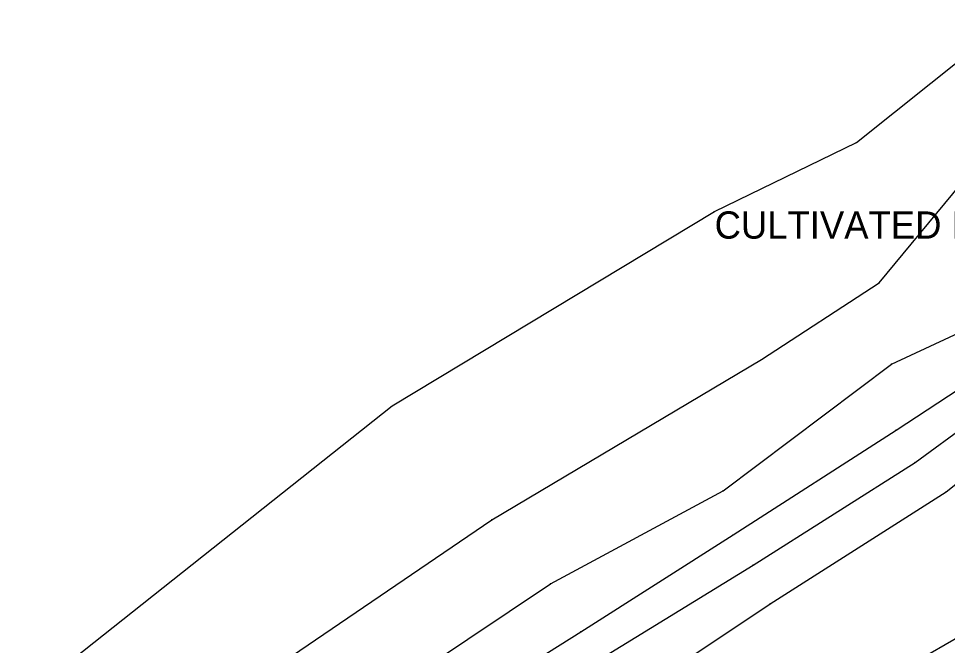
# Model space of a CAD drawing. Extents: x 1419505 to 1434054, y 1956910 to 1968644.
# Drawn here: x 1422840.8 to 1423011.2, y 1959040 to 1959155 of the extents above; entities that cross this region are included whole.
import ezdxf

# ---------------------------------------------------------------- set-up
doc = ezdxf.new("R2010")
doc.units = 0
for name, color, linetype in [('S_BREAKLINE', 7, 'Continuous'), ('S_DITCHLINE', 7, 'Continuous'), ('S_GRD_PT_SYM', 7, 'Continuous'), ('S_MSC_PT_SYM', 7, 'Continuous'), ('S_SURVEY_TEXT_ANNOT', 7, 'Continuous')]:
    doc.layers.add(name, color=color, linetype=linetype)

msp = doc.modelspace()

# ---------------------------------------------------------------- linework, layer by layer
at = {"layer": 'S_BREAKLINE'}
for p, q in [((1422994.5276, 1959132.2688), (1423022.9164, 1959155.0183)), ((1422998.6778, 1959106.5561), (1423022.2564, 1959135.109)), ((1422968.4779, 1959119.635), (1422994.5276, 1959132.2688)), ((1422909.3401, 1959083.9587), (1422968.4779, 1959119.635)), ((1422977.0964, 1959092.4572), (1422998.6778, 1959106.5561)), ((1423000.908, 1959091.6272), (1423029.8858, 1959105.094)), ((1422927.6052, 1959063.1023), (1422977.0964, 1959092.4572)), ((1422970.015, 1959068.3897), (1423000.908, 1959091.6272)), ((1423010.9586, 1959068.1907), (1423034.6522, 1959087.3959)), ((1422840.7776, 1959029.6612), (1422909.3401, 1959083.9587)), ((1422938.3659, 1959051.3316), (1422970.015, 1959068.3897)), ((1422978.6695, 1959047.6883), (1423010.9586, 1959068.1907)), ((1422864.9112, 1959020.4656), (1422927.6052, 1959063.1023)), ((1422881.2152, 1959013.1311), (1422938.3659, 1959051.3316)), ((1422950.6087, 1959028.9581), (1422978.6695, 1959047.6883)), ((1422987.9141, 1959027.032), (1423022.4534, 1959046.9853))]:
    msp.add_line(p, q, dxfattribs=at)
at = {"layer": 'S_DITCHLINE'}
for p, q in [((1423001.755, 1959079.5054), (1423029.9539, 1959098.0626)), ((1423005.2653, 1959073.577), (1423033.1021, 1959094.1543)), ((1422971.8951, 1959060.3062), (1423001.755, 1959079.5054)), ((1422975.5353, 1959054.7468), (1423005.2653, 1959073.577)), ((1422943.9453, 1959042.53), (1422971.8951, 1959060.3062)), ((1422945.9684, 1959036.6096), (1422975.5353, 1959054.7468)), ((1422890.9719, 1959009.3679), (1422943.9453, 1959042.53))]:
    msp.add_line(p, q, dxfattribs=at)
at = {"layer": 'S_GRD_PT_SYM'}
for points in [[(1422994.5276, 1959132.2688), (1422994.5276, 1959132.3188), (1422994.5276, 1959132.2688), (1422994.4776, 1959132.2688), (1422994.5276, 1959132.2688), (1422994.5276, 1959132.2188), (1422994.5276, 1959132.2688), (1422994.5776, 1959132.2688)], [(1422968.4779, 1959119.635), (1422968.4779, 1959119.685), (1422968.4779, 1959119.635), (1422968.4279, 1959119.635), (1422968.4779, 1959119.635), (1422968.4779, 1959119.585), (1422968.4779, 1959119.635), (1422968.5279, 1959119.635)], [(1422998.6778, 1959106.5561), (1422998.6778, 1959106.6061), (1422998.6778, 1959106.5561), (1422998.6278, 1959106.5561), (1422998.6778, 1959106.5561), (1422998.6778, 1959106.5061), (1422998.6778, 1959106.5561), (1422998.7278, 1959106.5561)], [(1422977.0964, 1959092.4572), (1422977.0964, 1959092.5072), (1422977.0964, 1959092.4572), (1422977.0464, 1959092.4572), (1422977.0964, 1959092.4572), (1422977.0964, 1959092.4072), (1422977.0964, 1959092.4572), (1422977.1464, 1959092.4572)], [(1423000.908, 1959091.6272), (1423000.908, 1959091.6772), (1423000.908, 1959091.6272), (1423000.858, 1959091.6272), (1423000.908, 1959091.6272), (1423000.908, 1959091.5772), (1423000.908, 1959091.6272), (1423000.958, 1959091.6272)], [(1422909.3401, 1959083.9587), (1422909.3401, 1959084.0087), (1422909.3401, 1959083.9587), (1422909.2901, 1959083.9587), (1422909.3401, 1959083.9587), (1422909.3401, 1959083.9087), (1422909.3401, 1959083.9587), (1422909.3901, 1959083.9587)], [(1423001.755, 1959079.5054), (1423001.755, 1959079.5554), (1423001.755, 1959079.5054), (1423001.705, 1959079.5054), (1423001.755, 1959079.5054), (1423001.755, 1959079.4554), (1423001.755, 1959079.5054), (1423001.805, 1959079.5054)], [(1423005.2653, 1959073.577), (1423005.2653, 1959073.627), (1423005.2653, 1959073.577), (1423005.2153, 1959073.577), (1423005.2653, 1959073.577), (1423005.2653, 1959073.527), (1423005.2653, 1959073.577), (1423005.3153, 1959073.577)], [(1422970.015, 1959068.3897), (1422970.015, 1959068.4397), (1422970.015, 1959068.3897), (1422969.965, 1959068.3897), (1422970.015, 1959068.3897), (1422970.015, 1959068.3397), (1422970.015, 1959068.3897), (1422970.065, 1959068.3897)], [(1423010.9586, 1959068.1907), (1423010.9586, 1959068.2407), (1423010.9586, 1959068.1907), (1423010.9086, 1959068.1907), (1423010.9586, 1959068.1907), (1423010.9586, 1959068.1407), (1423010.9586, 1959068.1907), (1423011.0086, 1959068.1907)], [(1422927.6052, 1959063.1023), (1422927.6052, 1959063.1523), (1422927.6052, 1959063.1023), (1422927.5552, 1959063.1023), (1422927.6052, 1959063.1023), (1422927.6052, 1959063.0523), (1422927.6052, 1959063.1023), (1422927.6552, 1959063.1023)], [(1422971.8951, 1959060.3062), (1422971.8951, 1959060.3562), (1422971.8951, 1959060.3062), (1422971.8451, 1959060.3062), (1422971.8951, 1959060.3062), (1422971.8951, 1959060.2562), (1422971.8951, 1959060.3062), (1422971.9451, 1959060.3062)], [(1422975.5353, 1959054.7468), (1422975.5353, 1959054.7968), (1422975.5353, 1959054.7468), (1422975.4853, 1959054.7468), (1422975.5353, 1959054.7468), (1422975.5353, 1959054.6968), (1422975.5353, 1959054.7468), (1422975.5853, 1959054.7468)], [(1422938.3659, 1959051.3316), (1422938.3659, 1959051.3816), (1422938.3659, 1959051.3316), (1422938.3159, 1959051.3316), (1422938.3659, 1959051.3316), (1422938.3659, 1959051.2816), (1422938.3659, 1959051.3316), (1422938.4159, 1959051.3316)], [(1422978.6695, 1959047.6883), (1422978.6695, 1959047.7383), (1422978.6695, 1959047.6883), (1422978.6195, 1959047.6883), (1422978.6695, 1959047.6883), (1422978.6695, 1959047.6383), (1422978.6695, 1959047.6883), (1422978.7195, 1959047.6883)], [(1422943.9453, 1959042.53), (1422943.9453, 1959042.58), (1422943.9453, 1959042.53), (1422943.8953, 1959042.53), (1422943.9453, 1959042.53), (1422943.9453, 1959042.48), (1422943.9453, 1959042.53), (1422943.9953, 1959042.53)]]:
    msp.add_lwpolyline(points, dxfattribs=at)
at = {"layer": 'S_MSC_PT_SYM'}
msp.add_lwpolyline([(1422968.4719, 1959119.654), (1422968.4719, 1959119.704), (1422968.4719, 1959119.654), (1422968.4219, 1959119.654), (1422968.4719, 1959119.654), (1422968.4719, 1959119.604), (1422968.4719, 1959119.654), (1422968.5219, 1959119.654)], dxfattribs=at)

# ---------------------------------------------------------------- texts
at = {"layer": 'S_SURVEY_TEXT_ANNOT'}
msp.add_text('CULTIVATED FIELD', height=5, dxfattribs=at).set_placement((1422968.4719, 1959114.654))

doc.saveas('drawing.dxf')
